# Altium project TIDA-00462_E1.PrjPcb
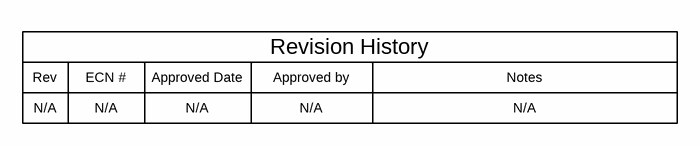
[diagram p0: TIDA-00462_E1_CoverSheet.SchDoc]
CopyrightYear: 2015; EVM_Orderable: N/A; PCB_Layout: Avinash; PCB_Rev: E1; PRJ_Customer: Public Release; PRJ_Engineer: FA&C; PRJ_Number: TIDA-00462; PRJ_Title: MSP430 MCU based Ultrasonic Distance Measurement; SCH_Rev: E1; TechSupport: http://www.ti.com/support; TID: TIDA-00462
4 sheets, 107 parts. Net scope: global (net labels, ports and power ports of the same name join across sheets).
Board file: TIDA-00462_E1.PcbDoc
Sheets:
  TIDA-00462_E1_CoverSheet.SchDoc
  TIDA-00462_E1_Power_Supply.SchDoc
  TIDA-00462_E1_MCU_US_TX_RX.SchDoc
  TIDA-00462_E1_TID_Hardware.SchDoc

## Sheet TIDA-00462_E1_CoverSheet.SchDoc: Block Diagram
size 431 x 279 mm; Date: Not shown in title block; ApprovedBy: Not shown in title block; CheckedBy: Not shown in title block; Author: Not shown in title block; CompanyName: Not shown in title block; DrawnBy: SY; Engineer: FA&C; Organization: Not shown in title block; Address1: Not shown in title block; Address2: Not shown in title block; Address3: Not shown in title block; Address4: Not shown in title block; DocumentNumber: 1; Revision: Use project parameter SCH_Rev; SheetNumber: 1; SheetTotal: 4; PageSetup: Record=PageOptions¦CenterHorizontal=True¦CenterVertical=True¦PrintScale=1.00¦XCorrection=1.00¦YCorrection=1.00¦PrintKind=0¦BorderSize=5000000¦LeftOffset=0¦BottomOffset=0¦Orientation=2¦PaperLength=1000¦PaperWidth=1000¦Scale=100¦PaperSource=15¦PrintQuality=600¦MediaType=1¦DitherType=10¦PaperKind=Letter¦PrintScaleMode=1

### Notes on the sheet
- Rev
- N/A
- ECN #
- Approved Date
- Approved by
- Revision History
- Notes

## Sheet TIDA-00462_E1_Power_Supply.SchDoc: Power Supply Circuitry & BP Connector
size 431 x 279 mm; Date: Not shown in title block; ApprovedBy: Not shown in title block; CheckedBy: Not shown in title block; Author: Not shown in title block; CompanyName: Not shown in title block; DrawnBy: SY; Engineer: FA&C; Organization: Not shown in title block; Address1: Not shown in title block; Address2: Not shown in title block; Address3: Not shown in title block; Address4: Not shown in title block; DocumentNumber: 1; Revision: Use project parameter SCH_Rev; SheetNumber: 2; SheetTotal: 4; PageSetup: Record=PageOptions¦CenterHorizontal=True¦CenterVertical=True¦PrintScale=1.00¦XCorrection=1.00¦YCorrection=1.00¦PrintKind=0¦BorderSize=5000000¦LeftOffset=0¦BottomOffset=0¦Orientation=2¦PaperLength=1000¦PaperWidth=1000¦Scale=100¦PaperSource=15¦PrintQuality=600¦MediaType=1¦DitherType=10¦PaperKind=Letter¦PrintScaleMode=1
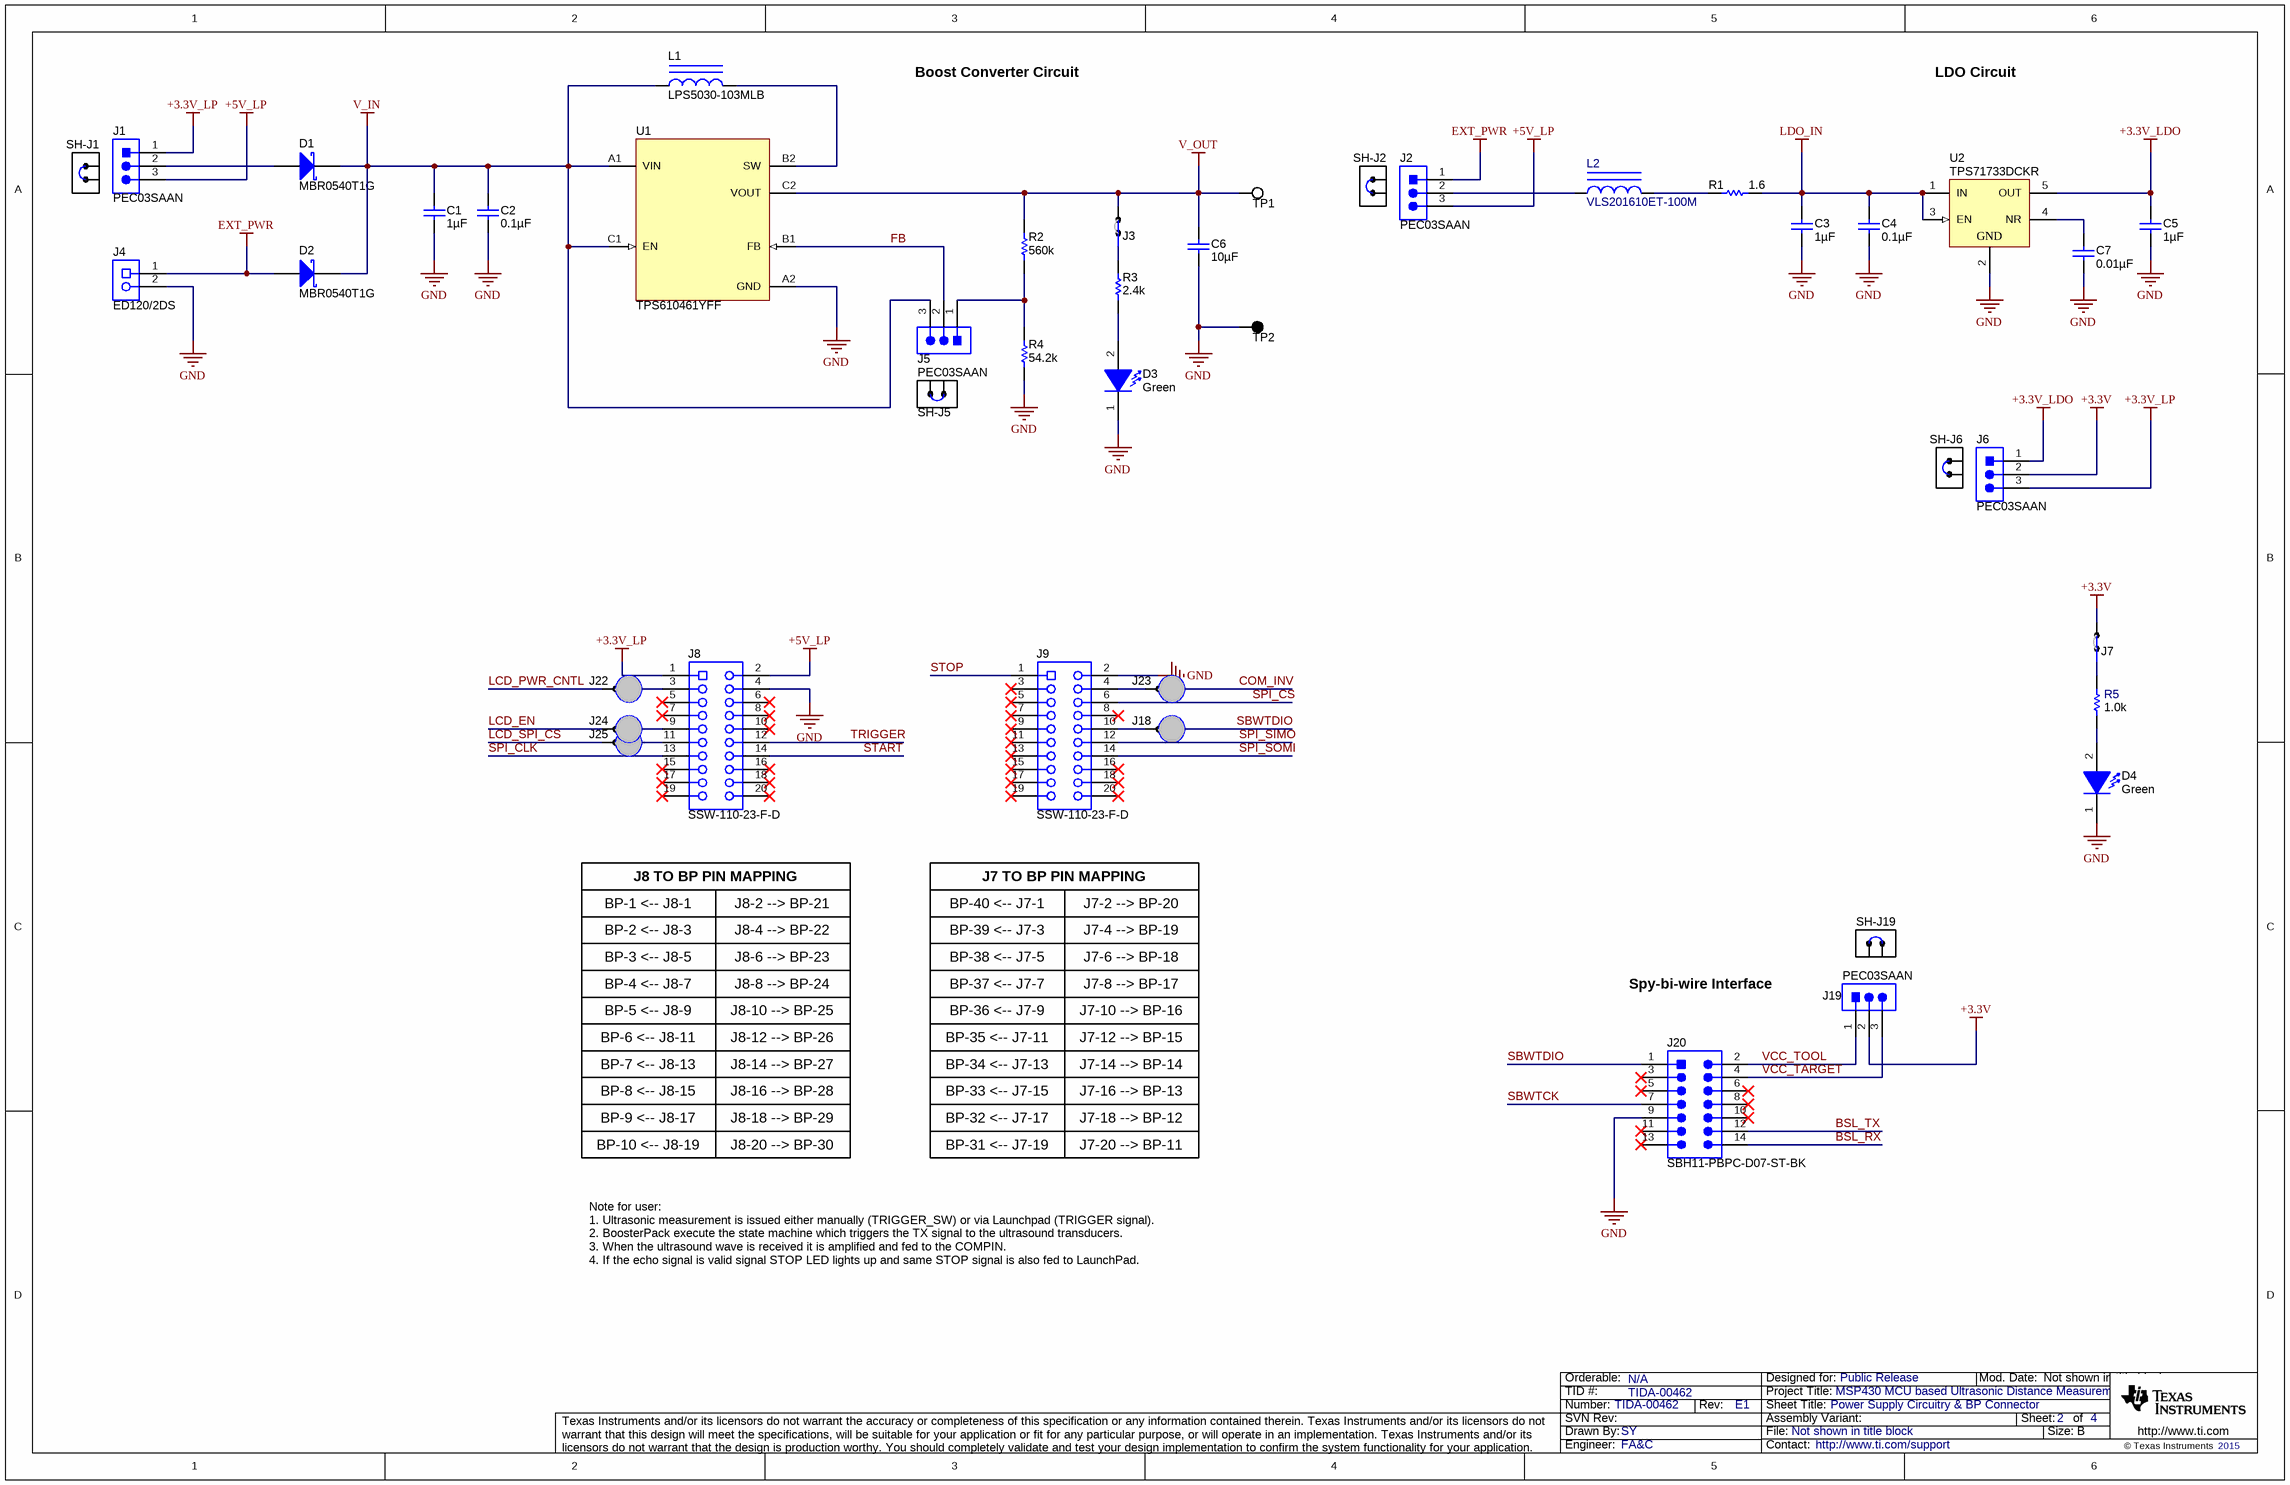
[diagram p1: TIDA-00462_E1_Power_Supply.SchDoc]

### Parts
C1  ValueDisplayed: 1µF  [0603]  (hidden comment: C1608X7R1C105K)
C2  ValueDisplayed: 0.1µF  [0603]  (hidden comment: C0603C104M4RACTU)
C3  ValueDisplayed: 1µF  [0603]  (hidden comment: GRM188R71E105KA12D)
C4  ValueDisplayed: 0.1µF  [0402]  (hidden comment: C1005X7R1H104K050BB)
C5  ValueDisplayed: 1µF  [0603]  (hidden comment: GRM188R71E105KA12D)
C6  ValueDisplayed: 10µF  [1206]  (hidden comment: GMK316AB7106KL)
C7  ValueDisplayed: 0.01µF  [0402]  (hidden comment: C1005X7R1C103K)
D1  MBR0540T1G  [SOD-123]
D2  MBR0540T1G  [SOD-123]
D3  value Green  [WL-SMCW_GREEN]  (hidden comment: 150060VS75000)
D4  value Green  [WL-SMCW_GREEN]  (hidden comment: 150060VS75000)
J1  PEC03SAAN  [CONN_PEC03SAAN]
J2  PEC03SAAN  [CONN_PEC03SAAN]
J3  923345-01-C  [3M_923345-01-C]  (value not drawn)
J4  ED120/2DS  [CONN_ED120-2DS]
J5  PEC03SAAN  [CONN_PEC03SAAN]
J6  PEC03SAAN  [CONN_PEC03SAAN]
J7  923345-01-C  [3M_923345-01-C]  (value not drawn)
J8  SSW-110-23-F-D  [CONN_SSW-110-23-F-D]
J9  SSW-110-23-F-D  [CONN_SSW-110-23-F-D]
J18  923345-01-C  [3M_923345-01-C]  (value not drawn)
J19  PEC03SAAN  [CONN_PEC03SAAN]
J20  SBH11-PBPC-D07-ST-BK  [CONN_SBH11-PBPC-D07-ST-BK]
J22  923345-01-C  [3M_923345-01-C]  (value not drawn)
J23  923345-01-C  [3M_923345-01-C]  (value not drawn)
J24  923345-01-C  [3M_923345-01-C]  (value not drawn)
J25  923345-01-C  [3M_923345-01-C]  (value not drawn)
L1  LPS5030-103MLB  [LPS5030]
L2  VLS201610ET-100M  [VLS201610]
R1  ValueDisplayed: 1.6  [0805]  (hidden comment: ERJ-6GEYJ1R6V)
R2  ValueDisplayed: 560k  [0603]  (hidden comment: RC0603FR-07560KL)
R3  ValueDisplayed: 2.4k  [0603]  (hidden comment: CRCW06032K40JNEA)
R4  ValueDisplayed: 54.2k  [0603]  (hidden comment: RT0603DRE0754K2L)
R5  value 1.0k  [0402]  (hidden comment: CRCW04021K00JNED)
SH-J1  969102-0000-DA  [SNT-100-BK-G]  (value not drawn)
SH-J2  969102-0000-DA  [SNT-100-BK-G]  (value not drawn)
SH-J5  969102-0000-DA  [SNT-100-BK-G]  (value not drawn)
SH-J6  969102-0000-DA  [SNT-100-BK-G]  (value not drawn)
SH-J19  969102-0000-DA  [SNT-100-BK-G]  (value not drawn)
TP1  5002  [Keystone5002]  (value not drawn)
TP2  5001  [Keystone5001]  (value not drawn)
U1  TPS610461YFF  [YFF0006AAAA]
U2  TPS71733DCKR  [DCK0005A_N]

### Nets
+3.3V: J6.2 J7.2 J19.2
+3.3V_LDO: C5.1 J6.1 U2.5(OUT)
+3.3V_LP: J1.1 J6.3 J8.1
+5V_LP: J1.3 J2.3 J8.2
EXT_PWR: D2.2(A) J2.1 J4.1
GND: C1.2 C2.2 C3.2 C4.2 C5.2 C6.2 C7.2 D3.1(K) D4.1(K) J4.2 J8.4 J9.2 J20.9 R4.1 TP2.1 U1.A2(GND) U2.2(GND)
LDO_IN: C3.1 C4.1 R1.2 U2.1(IN) U2.3(EN)
V_IN: C1.1 C2.1 D1.1(K) D2.1(K) J5.3 L1.1 U1.A1(VIN) U1.C1(EN)
V_OUT: C6.1 J3.2 R2.2 TP1.1 U1.C2(VOUT)
BSL_RX: J20.14
BSL_TX: J20.12
COM_INV: J23.1
FB: J5.2 U1.B1(FB)
LCD_EN: J24.2
LCD_PWR_CNTL: J22.2
LCD_SPI_CS: J25.2
SBWTCK: J20.7
SBWTDIO: J18.1 J20.1
SPI_CLK: J8.13
SPI_CS: J9.6
SPI_SIMO: J9.12
SPI_SOMI: J9.14
START: J8.14
STOP: J9.1
TRIGGER: J8.12
VCC_TARGET: J19.3 J20.4
VCC_TOOL: J19.1 J20.2
NetC7_1: C7.1 U2.4(NR)
NetD1_2: D1.2(A) J1.2
NetD3_2: D3.2(A) R3.1
NetD4_2: D4.2(A) R5.2
NetJ2_2: J2.2 L2.1
NetJ3_1: J3.1 R3.2
NetJ5_1: J5.1 R2.1 R4.2
NetJ7_1: J7.1 R5.1
NetJ8_3: J8.3 J22.1
NetJ8_9: J8.9 J24.1
NetJ8_11: J8.11 J25.1
NetJ9_4: J9.4 J23.2
NetJ9_10: J9.10 J18.2
NetL1_2: L1.2 U1.B2(SW)
NetL2_2: L2.2 R1.1

Not connected (* = marked no-connect by the designer): J8 5* 6* 7* 8* 10* 15* 16* 17* 18* 19* 20*; J9 3* 5* 7* 8* 9* 11* 13* 15* 16* 17* 18* 19* 20*; J20 3* 5* 6* 8* 10* 11* 13*

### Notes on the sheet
- Boost Converter Circuit
- LDO Circuit
- BP-1 <-- J8-1
- J8 TO BP PIN MAPPING
- J8-2 --> BP-21
- BP-40 <-- J7-1
- J7 TO BP PIN MAPPING
- J7-2 --> BP-20
- BP-2 <-- J8-3
- BP-3 <-- J8-5
- J8-4 --> BP-22
- J8-6 --> BP-23
- BP-39 <-- J7-3
- BP-38 <-- J7-5
- J7-4 --> BP-19
- J7-6 --> BP-18
- BP-4 <-- J8-7
- BP-5 <-- J8-9
- BP-6 <-- J8-11
- J8-8 --> BP-24
- J8-10 --> BP-25
- J8-12 --> BP-26
- BP-37 <-- J7-7
- BP-36 <-- J7-9
- BP-35 <-- J7-11
- J7-8 --> BP-17
- J7-10 --> BP-16
- J7-12 --> BP-15
- Spy-bi-wire Interface
- BP-7 <-- J8-13
- BP-8 <-- J8-15
- J8-14 --> BP-27
- J8-16 --> BP-28
- BP-34 <-- J7-13
- BP-33 <-- J7-15
- J7-14 --> BP-14
- J7-16 --> BP-13
- BP-10 <-- J8-19
- BP-9 <-- J8-17
- J8-18 --> BP-29
- J8-20 --> BP-30
- BP-31 <-- J7-19
- BP-32 <-- J7-17
- J7-18 --> BP-12
- J7-20 --> BP-11
- Note for user:
  1. Ultrasonic measurement is issued either manually (TRIGGER_SW) or via Launchpad (TRIGGER signal).
  2. BoosterPack execute the state machine which triggers the TX signal to the ultrasound transducers.
  3. When the ultrasound wave is received it is amplified and fed to the COMPIN.
  4. If the echo signal is valid signal STOP LED lights up and same STOP signal is also fed to LaunchPad.

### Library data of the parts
C1 = C1608X7R1C105K: CAP, CERM, 1 µF, 16 V, +/- 10%, X7R, 0603; Manufacturer: TDK; Polarized: N; CompType: Capacitor; Value: 1uF; U/M: EA; Cap_F: 0.000001; Tolerance_%: 10; ESR_ohm: 0.0057; Value1: 0.0057 ohm; VDC_V: 16; Value2: 16V; TaMin_C: -55; TaMax_C: 125
C2 = C0603C104M4RACTU: CAP, CERM, 0.1 µF, 16 V, +/- 20%, X7R, 0603; Manufacturer: Kemet; Polarized: N; CompType: Capacitor; Value: 0.1uF; U/M: EA; Cap_F: 0.0000001; Tolerance_%: 20; Value1: Unknown; VDC_V: 16; Value2: 16V; TaMin_C: -55; TaMax_C: 125
C3 C5 = GRM188R71E105KA12D: CAP, CERM, 1 µF, 25 V, +/- 10%, X7R, 0603; Manufacturer: MuRata; Polarized: N; CompType: Capacitor; Value: 1uF; U/M: EA; Cap_F: 0.000001; Tolerance_%: 10; Value1: Unknown; VDC_V: 25; Value2: 25V; TaMin_C: -55; TaMax_C: 125
C4 = C1005X7R1H104K050BB: CAP, CERM, 0.1 µF, 50 V, +/- 10%, X7R, 0402; Manufacturer: TDK; Polarized: N; CompType: Capacitor; Value: 0.1uF; U/M: EA; Cap_F: 0.0000001; Tolerance_%: 10; Value1: Unknown; VDC_V: 50; Value2: 50V; TaMin_C: -55; TaMax_C: 125
C6 = GMK316AB7106KL: CAP, CERM, 10 µF, 35 V, +/- 10%, X7R, 1206; Manufacturer: Taiyo Yuden; Polarized: N; CompType: Capacitor; Value: 10uF; U/M: EA; Cap_F: 0.00001; Tolerance_%: 10; Value1: Unknown; VDC_V: 35; Value2: 35V; TaMin_C: -55; TaMax_C: 125
C7 = C1005X7R1C103K: CAP, CERM, 0.01 µF, 16 V, +/- 10%, X7R, 0402; Manufacturer: TDK; Polarized: N; CompType: Capacitor; Value: 0.01uF; U/M: EA; Cap_F: 0.00000001; Tolerance_%: 10; ESR_ohm: 0.0623; Value1: 0.0623 ohm; VDC_V: 16; Value2: 16V; TaMin_C: -55; TaMax_C: 125
D1 D2 = MBR0540T1G: Diode, Schottky, 40V, 0.5A, SOD-123; Manufacturer: ON Semiconductor; U/M: EA; Vf_V: 0.51; Value2: 0.51V; Io_A: 0.5; Vr_V: 40; TJmax_C: 150; RJC_CperW: 118
D3 D4 = 150060VS75000: LED, Green, SMD; Manufacturer: Wurth Elektronik eiSos; Type: AlInGaP; Vf_V: 2; Value2: 2V; Io_A: 0.02; Value1: W; U/M: EA
J1 J2 J5 J6 J19 = PEC03SAAN: Header, 100mil, 3x1, Tin plated, TH; Manufacturer: Sullins Connector Solutions; SymbolCreator: a0799628; U/M: EA
J3 J7 J18 J22-J25 = 923345-01-C: Jumper Wire, 100mil spacing, pkg of 200, TH; Manufacturer: 3M; SymbolCreator: Altium; U/M: EA
J4 = ED120/2DS: TERMINAL BLOCK 5.08MM VERT 2POS, TH; Manufacturer: On-Shore Technology; SymbolCreator: a0412235; U/M: EA
J8 J9 = SSW-110-23-F-D: Connector, Receptacle, 100mil, 10x2, Gold plated, TH; Manufacturer: Samtec; SymbolCreator: a0412235; U/M: EA
J20 = SBH11-PBPC-D07-ST-BK: Header (shrouded), 100 mil, 7x2, Gold plated, TH; Manufacturer: Sullins Connector Solutions; SymbolCreator: a0412235; CompType: Connector; U/M: EA
L1 = LPS5030-103MLB: Inductor, Shielded Drum Core, Ferrite, 10 µH, 1.4 A, 0.13 ohm, SMD; Manufacturer: Coilcraft; Value: 10uH; Ind_H: 10.0E-6; ValueDisplayed: 10µH; Imax_A: 1.4; Irms: 1.5A @ 40C rise; Isat: 1.4A @ 30% inductance drop; DCR_ohm: 0.13; Value2: 1.4A
L2 = VLS201610ET-100M: Inductor, Shielded, Ferrite, 10uH, 0.4A, 1.38 ohm, SMD; Manufacturer: TDK; Ind_H: 10.0E-6; ValueDisplayed: 10µH; Imax_A: 0.4; Irms: 0.42A @ 40C rise; Isat: 0.4A @ 30% inductance drop; DCR_ohm: 1.38; U/M: EA
R1 = ERJ-6GEYJ1R6V: RES, 1.6, 5%, 0.125 W, 0805; Manufacturer: Panasonic; CompType: Resistor; Value: 1.6; Value_Code: 1R60; Tolerance_%: 5; Power_W: 0.125; Value2: 0.125W; VDC_V: 150; TempCo: 600 ppm/C; EIA_Code: E24; U/M: EA
R2 = RC0603FR-07560KL: RES, 560 k, 1%, 0.1 W, 0603; Manufacturer: Yageo America; CompType: Resistor; Value: 560k; Res_ohm: 560000; Tolerance_%: 1; Power_W: 0.1; Value2: 0.1W; VDC_V: 150; TempCo: 200 ppm/C; U/M: EA
R3 = CRCW06032K40JNEA: RES, 2.4 k, 5%, 0.1 W, 0603; Manufacturer: Vishay-Dale; CompType: Resistor; Value: 2.4k; Res_ohm: 2400; Value_Code: 2k40; Tolerance_%: 5; Power_W: 0.1; Value2: 0.1W; VDC_V: 75; TempCo: 200 ppm/C; EIA_Code: E24; U/M: EA
R4 = RT0603DRE0754K2L: RES, 54.2 k, 0.5%, 0.1 W, 0603; Manufacturer: Yageo America; CompType: Resistor; Value: 54.2k; Res_ohm: 54200; Value_Code: 54k2; Tolerance_%: 0.5; Power_W: 0.1; Value2: 0.1W; VDC_V: 75; TempCo: 50 ppm/C; EIA_Code: E192; U/M: EA
R5 = CRCW04021K00JNED: RES, 1.0k ohm, 5%, 0.063W, 0402; Manufacturer: Vishay-Dale; CompType: Resistor; Res_ohm: 1000; Value_Code: 1k00; Tolerance_%: 5; Power_W: 0.063; VDC_V: 50; TempCo: 200 ppm/C; EIA_Code: E24; U/M: EA
SH-J1 SH-J2 SH-J5 SH-J6 SH-J19 = 969102-0000-DA: Shunt, 100mil, Gold plated, Black; Manufacturer: 3M; Alternate Manufacturer: Samtec; Value: 1x2; Note: You can "mate" this to a header by matching the designator.  i.e. use SH-J3 for header J3
TP1 = 5002: Test Point, Miniature, White, TH; Manufacturer: Keystone; CompType: Test Point Loop; U/M: EA
TP2 = 5001: Test Point, Miniature, Black, TH; Manufacturer: Keystone; CompType: Test Point Loop; U/M: EA
U1 = TPS610461YFF: 28-V Output Voltage Boost Converter, YFF0006AAAA; Manufacturer: Texas Instruments; SymbolCreator: Altium; CompType: IC; U/M: EA
U2 = TPS71733DCKR: Single Output High PSRR LDO, 150 mA, Fixed 3.3 V Output, 2.5 to 6.5 V Input, with Low IQ, 5-pin SC70 (DCK), -40 to 85 degC, Green (RoHS & no Sb/Br); Manufacturer: Texas Instruments; Alternate Manufacturer: None; Alternate PartNumber: Equivalent; Accuracy(%): 3; Fixed Output Options(V): 3.3; Iout(Max)(A): 0.15; Iq(Typ)(mA): 0.05; SubFamily: Single Channel LDO; Vdo(Typ)(mV): 170; Vin(Max)(V): 6.5; Vin(Min)(V): 2.5

## Sheet TIDA-00462_E1_MCU_US_TX_RX.SchDoc: MSP430 MCU & US Sensor (TX & RX) Circuitry
size 431 x 279 mm; Date: Not shown in title block; ApprovedBy: Not shown in title block; CheckedBy: Not shown in title block; Author: Not shown in title block; CompanyName: Not shown in title block; DrawnBy: SY; Engineer: FA&C; Organization: Not shown in title block; Address1: Not shown in title block; Address2: Not shown in title block; Address3: Not shown in title block; Address4: Not shown in title block; DocumentNumber: 1; Revision: Use project parameter SCH_Rev; SheetNumber: 3; SheetTotal: 4; PageSetup: Record=PageOptions¦CenterHorizontal=True¦CenterVertical=True¦PrintScale=1.00¦XCorrection=1.00¦YCorrection=1.00¦PrintKind=0¦BorderSize=5000000¦LeftOffset=0¦BottomOffset=0¦Orientation=2¦PaperLength=1000¦PaperWidth=1000¦Scale=100¦PaperSource=15¦PrintQuality=600¦MediaType=1¦DitherType=10¦PrintScaleMode=1¦PaperKind=Letter
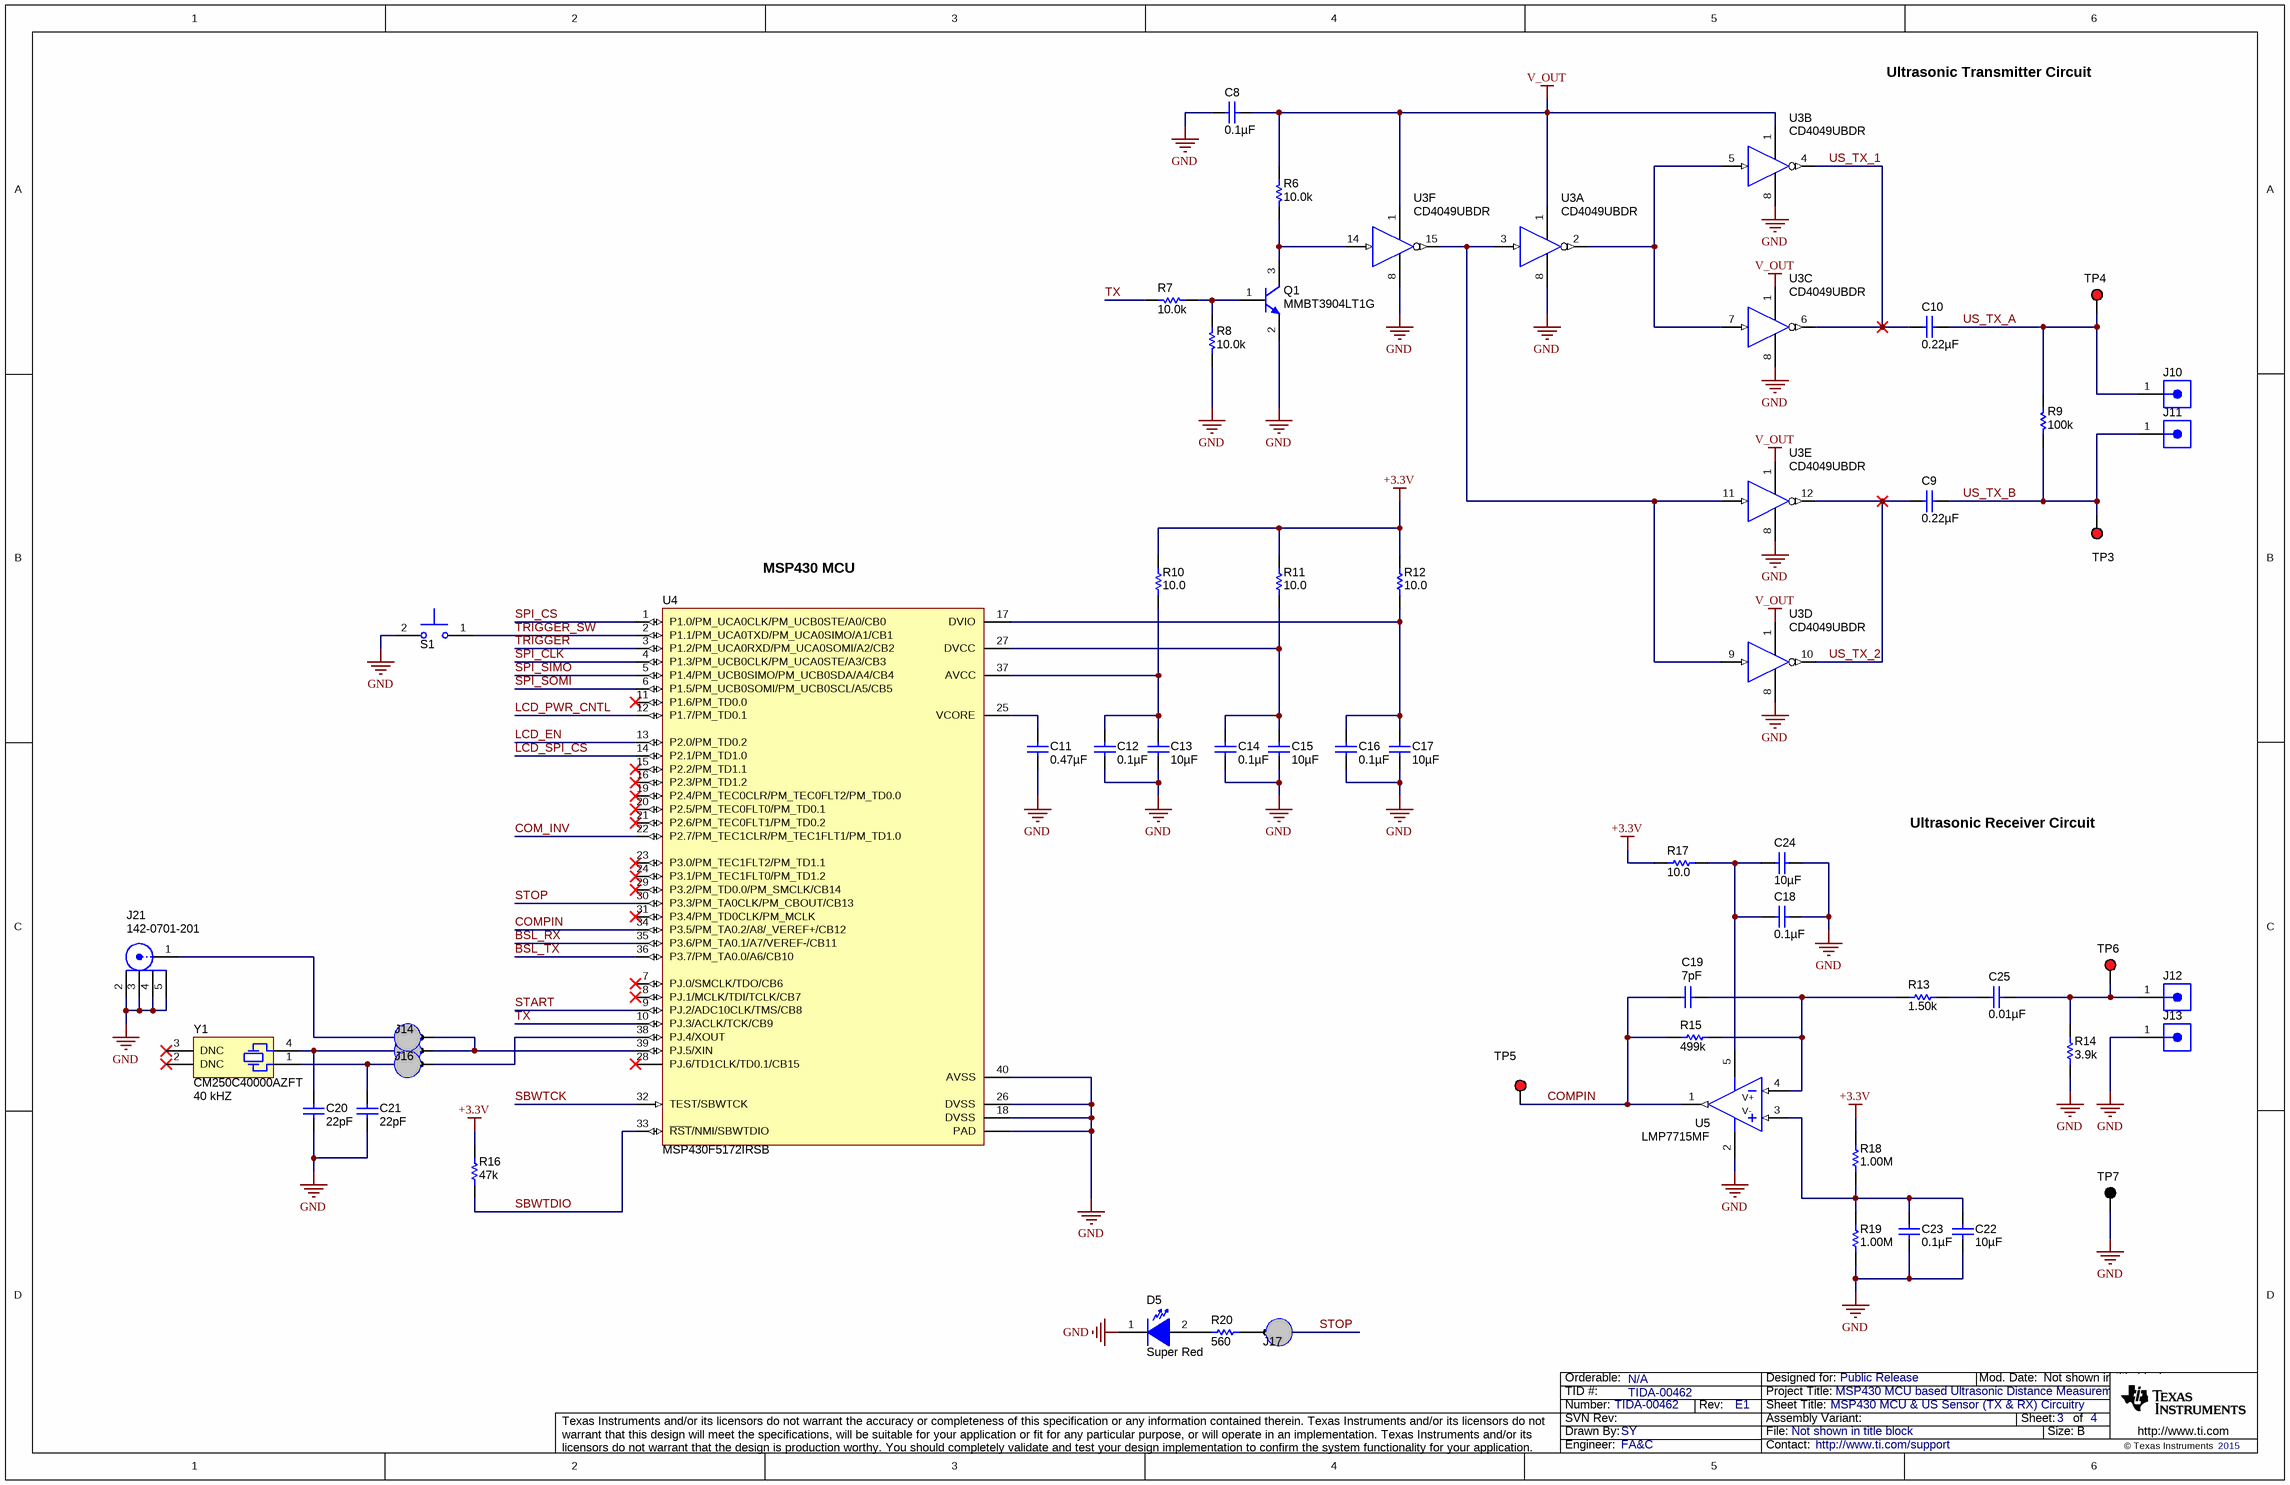
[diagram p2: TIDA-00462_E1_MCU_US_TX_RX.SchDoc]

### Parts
C8  ValueDisplayed: 0.1µF  [0402]  (hidden comment: C1005X7R1H104K050BB)
C9  ValueDisplayed: 0.22µF  [0603]  (hidden comment: C1608X7R1H224K080AB)
C10  ValueDisplayed: 0.22µF  [0603]  (hidden comment: C1608X7R1H224K080AB)
C11  ValueDisplayed: 0.47µF  [0603S]  (hidden comment: GRM188R70J474KA01D)
C12  ValueDisplayed: 0.1µF  [0402S]  (hidden comment: GRM155R70J104KA01D)
C13  ValueDisplayed: 10µF  [0402]  (hidden comment: CL05A106MQ5NUNC)
C14  ValueDisplayed: 0.1µF  [0402S]  (hidden comment: GRM155R70J104KA01D)
C15  ValueDisplayed: 10µF  [0402]  (hidden comment: CL05A106MQ5NUNC)
C16  ValueDisplayed: 0.1µF  [0402S]  (hidden comment: GRM155R70J104KA01D)
C17  ValueDisplayed: 10µF  [0402]  (hidden comment: CL05A106MQ5NUNC)
C18  ValueDisplayed: 0.1µF  [0402]  (hidden comment: C1005X7R1H104K050BB)
C19  ValueDisplayed: 7pF  [0805_HV]  (hidden comment: CC0805DRNP09BN7R0)
C20  ValueDisplayed: 22pF  [0402]  (hidden comment: C1005C0G1H220J050BA)
C21  ValueDisplayed: 22pF  [0402]  (hidden comment: C1005C0G1H220J050BA)
C22  ValueDisplayed: 10µF  [0805_145]  (hidden comment: 885012207026)
C23  ValueDisplayed: 0.1µF  [0402]  (hidden comment: C1005X7R1H104K050BB)
C24  ValueDisplayed: 10µF  [0402]  (hidden comment: CL05A106MQ5NUNC)
C25  ValueDisplayed: 0.01µF  [0603]  (hidden comment: GRM188R71C103KA01D)
D5  value Super Red  [WL-SMCW_RED]  (hidden comment: 150060SS75000)
J10  TSW-101-17-T-S  [Samtec_TSW-101-17-T-S]  (value not drawn)
J11  TSW-101-17-T-S  [Samtec_TSW-101-17-T-S]  (value not drawn)
J12  TSW-101-17-T-S  [Samtec_TSW-101-17-T-S]  (value not drawn)
J13  TSW-101-17-T-S  [Samtec_TSW-101-17-T-S]  (value not drawn)
J14  923345-01-C  [3M_923345-01-C]  (value not drawn)
J15  923345-01-C  [3M_923345-01-C]  (value not drawn)
J16  923345-01-C  [3M_923345-01-C]  (value not drawn)
J17  923345-01-C  [3M_923345-01-C]  (value not drawn)
J21  142-0701-201  [Johnson_142-0701-20x]
Q1  MMBT3904LT1G  [SOT-23]
R6  ValueDisplayed: 10.0k  [0603]  (hidden comment: ERJ-3EKF1002V)
R7  ValueDisplayed: 10.0k  [0603]  (hidden comment: ERJ-3EKF1002V)
R8  ValueDisplayed: 10.0k  [0603]  (hidden comment: ERJ-3EKF1002V)
R9  ValueDisplayed: 100k  [0603]  (hidden comment: RC0603FR-07100KL)
R10  value 10.0  [0603]  (hidden comment: CRCW060310R0FKEA)
R11  value 10.0  [0603]  (hidden comment: CRCW060310R0FKEA)
R12  value 10.0  [0603]  (hidden comment: CRCW060310R0FKEA)
R13  ValueDisplayed: 1.50k  [0603]  (hidden comment: ERJ-3EKF1501V)
R14  ValueDisplayed: 3.9k  [0603]  (hidden comment: CRCW06033K90JNEA)
R15  ValueDisplayed: 499k  [0603]  (hidden comment: CRCW0603499KFKEA)
R16  value 47k  [0402]  (hidden comment: CRCW040247K0JNED)
R17  value 10.0  [0603]  (hidden comment: CRCW060310R0FKEA)
R18  ValueDisplayed: 1.00M  [0603]  (hidden comment: CRCW06031M00FKEA)
R19  ValueDisplayed: 1.00M  [0603]  (hidden comment: CRCW06031M00FKEA)
R20  ValueDisplayed: 560  [0603]  (hidden comment: CRCW0603560RJNEA)
S1  SKRKAEE010  [SW_SKRKAEE010]  (value not drawn)
TP3  5000  [Keystone5000]  (value not drawn)
TP4  5000  [Keystone5000]  (value not drawn)
TP5  5000  [Keystone5000]  (value not drawn)
TP6  5000  [Keystone5000]  (value not drawn)
TP7  5001  [Keystone5001]  (value not drawn)
U3  CD4049UBDR  [D0016A_N]  (parts A,B,C,D,E,F of 7)
U4  MSP430F5172IRSB  [RSB0040B]
U5  LMP7715MF  [DBV0005A_N]
Y1  CM250C40000AZFT  Frequency: 40 kHZ  [CFM_CM250C]

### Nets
+3.3V: R10.2 R11.2 R12.2 R16.2 R17.2 R18.2
GND: C8.2 C11.2 C12.2 C13.2 C14.2 C15.2 C16.2 C17.2 C18.2 C20.2 C21.2 C22.2 C23.2 C24.2 D5.1(K) J13.1 J21.2 J21.3 J21.4 J21.5 Q1.2(E) R8.2 R14.1 R19.1 S1.2 TP7.1 U3.8(VSS) U4.18(DVSS) U4.26(DVSS) U4.40(AVSS) U4.41(PAD) U5.2(V-)
V_OUT: C8.1 R6.2 U3.1(VCC)
BSL_RX: U4.35(P3.6/PM_TA0.1/A7/VEREF-/CB11)
BSL_TX: U4.36(P3.7/PM_TA0.0/A6/CB10)
COM_INV: U4.22(P2.7/PM_TEC1CLR/PM_TEC1FLT1/PM_TD1.0)
COMPIN: C19.2 R15.1 TP5.1 U4.34(P3.5/PM_TA0.2/A8/_VEREF+/CB12) U5.1(OUT)
LCD_EN: U4.13(P2.0/PM_TD0.2)
LCD_PWR_CNTL: U4.12(P1.7/PM_TD0.1)
LCD_SPI_CS: U4.14(P2.1/PM_TD1.0)
SBWTCK: U4.32(TEST/SBWTCK)
SBWTDIO: R16.1 U4.33(~{RST}/NMI/SBWTDIO)
SPI_CLK: U4.4(P1.3/PM_UCB0CLK/PM_UCA0STE/A3/CB3)
SPI_CS: U4.1(P1.0/PM_UCA0CLK/PM_UCB0STE/A0/CB0)
SPI_SIMO: U4.5(P1.4/PM_UCB0SIMO/PM_UCB0SDA/A4/CB4)
SPI_SOMI: U4.6(P1.5/PM_UCB0SOMI/PM_UCB0SCL/A5/CB5)
START: U4.9(PJ.2/ADC10CLK/TMS/CB8)
STOP: J17.1 U4.30(P3.3/PM_TA0CLK/PM_CBOUT/CB13)
TRIGGER: U4.3(P1.2/PM_UCA0RXD/PM_UCA0SOMI/A2/CB2)
TRIGGER_SW: S1.1 U4.2(P1.1/PM_UCA0TXD/PM_UCA0SIMO/A1/CB1)
TX: R7.1 U4.10(PJ.3/ACLK/TCK/CB9)
US_TX_1: C10.2 U3.4(Y) U3.6(Y)
US_TX_2: C9.2 U3.10(Y) U3.12(Y)
US_TX_A: C10.1 J10.1 R9.1 TP4.1
US_TX_B: C9.1 J11.1 R9.2 TP3.1
NetC11_1: C11.1 U4.25(VCORE)
NetC12_1: C12.1 C13.1 R10.1 U4.37(AVCC)
NetC14_1: C14.1 C15.1 R11.1 U4.27(DVCC)
NetC16_1: C16.1 C17.1 R12.1 U4.17(DVIO)
NetC18_1: C18.1 C24.1 R17.1 U5.5(V+)
NetC19_1: C19.1 R13.1 R15.2 U5.4(IN-)
NetC20_1: C20.1 J15.1 Y1.4
NetC21_1: C21.1 J16.1 Y1.1
NetC22_1: C22.1 C23.1 R18.1 R19.2 U5.3(IN+)
NetC25_1: C25.1 J12.1 R14.2 TP6.1
NetC25_2: C25.2 R13.2
NetD5_2: D5.2(A) R20.1
NetJ14_1: J14.1 J21.1
NetJ14_2: J14.2 J15.2 U4.39(PJ.5/XIN)
NetJ16_2: J16.2 U4.38(PJ.4/XOUT)
NetJ17_2: J17.2 R20.2
NetQ1_1: Q1.1(B) R7.2 R8.1
NetQ1_3: Q1.3(C) R6.1 U3.14(A)
NetU3_2: U3.2(Y) U3.5(A) U3.7(A)
NetU3_3: U3.3(A) U3.9(A) U3.11(A) U3.15(Y)

Not connected (* = marked no-connect by the designer): U4 7(PJ.0/SMCLK/TDO/CB6)* 8(PJ.1/MCLK/TDI/TCLK/CB7)* 11(P1.6/PM_TD0.0)* 15(P2.2/PM_TD1.1)* 16(P2.3/PM_TD1.2)* 19(P2.4/PM_TEC0CLR/PM_TEC0FLT2/PM_TD0.0)* 20(P2.5/PM_TEC0FLT0/PM_TD0.1)* 21(P2.6/PM_TEC0FLT1/PM_TD0.2)* 23(P3.0/PM_TEC1FLT2/PM_TD1.1)* 24(P3.1/PM_TEC1FLT0/PM_TD1.2)* 28(PJ.6/TD1CLK/TD0.1/CB15)* 29(P3.2/PM_TD0.0/PM_SMCLK/CB14)* 31(P3.4/PM_TD0CLK/PM_MCLK)*; Y1 2(DNC)* 3(DNC)*

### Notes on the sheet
- Ultrasonic Transmitter Circuit
- (near U4) MSP430 MCU
- Ultrasonic Receiver Circuit

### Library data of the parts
C8 C18 C23 = C1005X7R1H104K050BB: as C4 on sheet TIDA-00462_E1_Power_Supply
C9 C10 = C1608X7R1H224K080AB: CAP, CERM, 0.22 µF, 50 V, +/- 10%, X7R, 0603; Manufacturer: TDK; Polarized: N; CompType: Capacitor; Value: 0.22uF; U/M: EA; Cap_F: 0.00000022; Tolerance_%: 10; Value1: Unknown; VDC_V: 50; Value2: 50V; TaMin_C: -55; TaMax_C: 125
C11 = GRM188R70J474KA01D: CAP, CERM, 0.47uF, 6.3V, +/-10%, X7R, 0603; Manufacturer: MuRata; Polarized: N; CompType: Capacitor; U/M: EA; Cap_F: 0.00000047; Tolerance_%: 10; Value1: Unknown; VDC_V: 6.3; TaMin_C: -55; TaMax_C: 125; Cap_Case: 0603
C12 C14 C16 = GRM155R70J104KA01D: CAP, CERM, 0.1uF, 6.3V, +/-10%, X7R, 0402; Manufacturer: MuRata; Polarized: N; CompType: Capacitor; U/M: EA; Cap_F: 0.0000001; Tolerance_%: 10; Value1: Unknown; VDC_V: 6.3; TaMin_C: -55; TaMax_C: 125; Cap_Case: 0402
C13 C15 C17 C24 = CL05A106MQ5NUNC: CAP, CERM, 10uF, 6.3V, +/-20%, X5R, 0402; Manufacturer: Samsung; Polarized: N; CompType: Capacitor; U/M: EA; Cap_F: 0.00001; Tolerance_%: 20; Value1: Unknown; VDC_V: 6.3; TaMin_C: -55; TaMax_C: 85
C19 = CC0805DRNP09BN7R0: CAP, CERM, 7 pF, 50 V, +/- 7%, C0G/NP0, 0805; Manufacturer: Yageo America; Polarized: N; CompType: Capacitor; Value: 7pF; U/M: EA; Cap_F: 0.000000000007; Tolerance_%: 7; Value1: Unknown; VDC_V: 50; Value2: 50V; TaMin_C: -55; TaMax_C: 125; Cap_Case: 0805
C20 C21 = C1005C0G1H220J050BA: CAP, CERM, 22 pF, 50 V, +/- 5%, C0G/NP0, 0402; Manufacturer: TDK; Polarized: N; CompType: Capacitor; Value: 22pF; U/M: EA; Cap_F: 0.000000000022; Tolerance_%: 5; Value1: Unknown; VDC_V: 50; Value2: 50V; TaMin_C: -55; TaMax_C: 125
C22 = 885012207026: CAP, CERM, 10 µF, 10 V, +/- 10%, X7R, 0805; Manufacturer: Wurth Elektronik; Polarized: N; CompType: Capacitor; Value: 10uF; U/M: EA; Cap_F: 0.00001; Tolerance_%: 10; Value1: Unknown; Value2: 10V; TaMin_C: -55; TaMax_C: 125; Cap_Case: 0805
C25 = GRM188R71C103KA01D: CAP, CERM, 0.01 µF, 16 V, +/- 10%, X7R, 0603; Manufacturer: MuRata; Polarized: N; CompType: Capacitor; Value: 0.01uF; U/M: EA; Cap_F: 0.00000001; Tolerance_%: 10; Value1: Unknown; VDC_V: 16; Value2: 16V; TaMin_C: -55; TaMax_C: 125
D5 = 150060SS75000: LED, Super Red, SMD; Manufacturer: Wurth Elektronik eiSos; Type: AlInGaP; Vf_V: 1.9; Value2: 1.9V; Io_A: 0.02; Value1: W; U/M: EA
J10-J13 = TSW-101-17-T-S: Header, 100mil, 1x1, Tin, TH; Manufacturer: Samtec; SymbolCreator: a0412235; U/M: EA
J14-J17 = 923345-01-C: as J3 on sheet TIDA-00462_E1_Power_Supply
J21 = 142-0701-201: Connector, TH, SMA; Manufacturer: Emerson Network Power; SymbolCreator: X0208326; U/M: EA
Q1 = MMBT3904LT1G, ON Semiconductor: Transistor, NPN, 40 V, 0.2 A, SOT-23; CompType: BJT; PNP: 0; NPN: 1; Vceo_V: 40; Vcesat1_V: 0.3; Value: 40 V; IcRated_A: 0.2; Value1: 0.2 A; HfeMax: 300; TaMin_C: -55; TaMax_C: 150; U/M: EA
R6-R8 = ERJ-3EKF1002V: RES, 10.0 k, 1%, 0.1 W, 0603; Manufacturer: Panasonic; CompType: Resistor; Value: 10.0k; Res_ohm: 10000; Value_Code: 10k0; Tolerance_%: 1; Power_W: 0.1; Value2: 0.1W; VDC_V: 75; TempCo: 100 ppm/C; EIA_Code: E96; U/M: EA
R9 = RC0603FR-07100KL: RES, 100 k, 1%, 0.1 W, 0603; Manufacturer: Yageo America; CompType: Resistor; Value: 100k; Res_ohm: 100000; Tolerance_%: 1; Power_W: 0.1; Value2: 0.1W; VDC_V: 150; TempCo: 200 ppm/C; EIA_Code: E96; U/M: EA
R10-R12 R17 = CRCW060310R0FKEA: RES, 10.0 ohm, 1%, 0.1W, 0603; Manufacturer: Vishay-Dale; CompType: Resistor; Res_ohm: 10; Value_Code: 10R0; Tolerance_%: 1; Power_W: 0.1; VDC_V: 75; TempCo: 100 ppm/C; EIA_Code: E96; U/M: EA
R13 = ERJ-3EKF1501V: RES, 1.50 k, 1%, 0.1 W, 0603; Manufacturer: Panasonic; CompType: Resistor; Value: 1.50k; Res_ohm: 1500; Value_Code: 1k50; Tolerance_%: 1; Power_W: 0.1; Value2: 0.1W; VDC_V: 75; TempCo: 100 ppm/C; EIA_Code: E96; U/M: EA
R14 = CRCW06033K90JNEA: RES, 3.9 k, 5%, 0.1 W, 0603; Manufacturer: Vishay-Dale; CompType: Resistor; Value: 3.9k; Res_ohm: 3900; Value_Code: 3k90; Tolerance_%: 5; Power_W: 0.1; Value2: 0.1W; VDC_V: 75; TempCo: 200 ppm/C; EIA_Code: E24; U/M: EA
R15 = CRCW0603499KFKEA: RES, 499 k, 1%, 0.1 W, 0603; Manufacturer: Vishay-Dale; CompType: Resistor; Value: 499k; Res_ohm: 499000; Tolerance_%: 1; Power_W: 0.1; Value2: 0.1W; VDC_V: 75; TempCo: 100 ppm/C; EIA_Code: E96; U/M: EA
R16 = CRCW040247K0JNED: RES, 47k ohm, 5%, 0.063W, 0402; Manufacturer: Vishay-Dale; CompType: Resistor; Res_ohm: 47000; Value_Code: 47k0; Tolerance_%: 5; Power_W: 0.063; VDC_V: 50; TempCo: 200 ppm/C; EIA_Code: E24; U/M: EA
R18 R19 = CRCW06031M00FKEA: RES, 1.00 M, 1%, 0.1 W, 0603; Manufacturer: Vishay-Dale; CompType: Resistor; Value: 1.00Meg; Res_ohm: 1000000; Value_Code: 1M00; Tolerance_%: 1; Power_W: 0.1; Value2: 0.1W; VDC_V: 75; TempCo: 100 ppm/C; EIA_Code: E96; U/M: EA
R20 = CRCW0603560RJNEA: RES, 560, 5%, 0.1 W, 0603; Manufacturer: Vishay-Dale; CompType: Resistor; Value: 560; Value_Code: 560R; Tolerance_%: 5; Power_W: 0.1; Value2: 0.1W; VDC_V: 75; TempCo: 200 ppm/C; EIA_Code: E24; U/M: EA
S1 = SKRKAEE010: Switch, Push Button, SMD; Manufacturer: Alps; SymbolCreator: a0412235; Circuit: SPST-NO; VDC_V: 12; SwitchFunction: Off-Mom; PositionCount: 1; CurrentRating_mA: 50
TP3-TP6 = 5000: Test Point, Miniature, Red, TH; Manufacturer: Keystone; CompType: Test Point Loop; U/M: EA
TP7 = 5001: as TP2 on sheet TIDA-00462_E1_Power_Supply
U3 = CD4049UBDR: CMOS Hex Buffer/Converters, D0016A; Alternate PartNumber: CD4049UBDT; Manufacturer: Texas Instruments; SymbolCreator: a0411947; CompType: IC; U/M: EA
U4 = MSP430F5172IRSB: Mixed Signal Microcontroller, RSB0040B; Alternate Manufacturer: None; Manufacturer: Texas Instruments; SymbolCreator: a0411947; CompType: IC; U/M: EA
U5 = LMP7715MF: 1.8V Precison, Single Low Noise CMOS Input Op Amp, DBV0005A; Manufacturer: Texas Instruments; CompType: OpAmp IC
Y1 = CM250C40000AZFT: Crystal, 40kHz, 12.5pF, SMD; Manufacturer: Citizen Finetech Miyota; SymbolCreator: a0411947; U/M: EA; TaMin_C: -40; TaMax_C: 85; Frequency Stability: ±30ppm

## Sheet TIDA-00462_E1_TID_Hardware.SchDoc: Hardware
size 431 x 279 mm; Date: Not shown in title block; ApprovedBy: Not shown in title block; CheckedBy: Not shown in title block; Author: Not shown in title block; CompanyName: Not shown in title block; DrawnBy: SY; Engineer: FA&C; Organization: Not shown in title block; Address1: Not shown in title block; Address2: Not shown in title block; Address3: Not shown in title block; Address4: Not shown in title block; DocumentNumber: 1; Revision: Use project parameter SCH_Rev; SheetNumber: 4; SheetTotal: 4; PageSetup: Record=PageOptions¦CenterHorizontal=True¦CenterVertical=True¦PrintScale=1.00¦XCorrection=1.00¦YCorrection=1.00¦PrintKind=0¦BorderSize=5000000¦LeftOffset=0¦BottomOffset=0¦Orientation=2¦PaperLength=1000¦PaperWidth=1000¦Scale=100¦PaperSource=15¦PrintQuality=600¦MediaType=1¦DitherType=10¦PaperKind=Letter¦PrintScaleMode=1
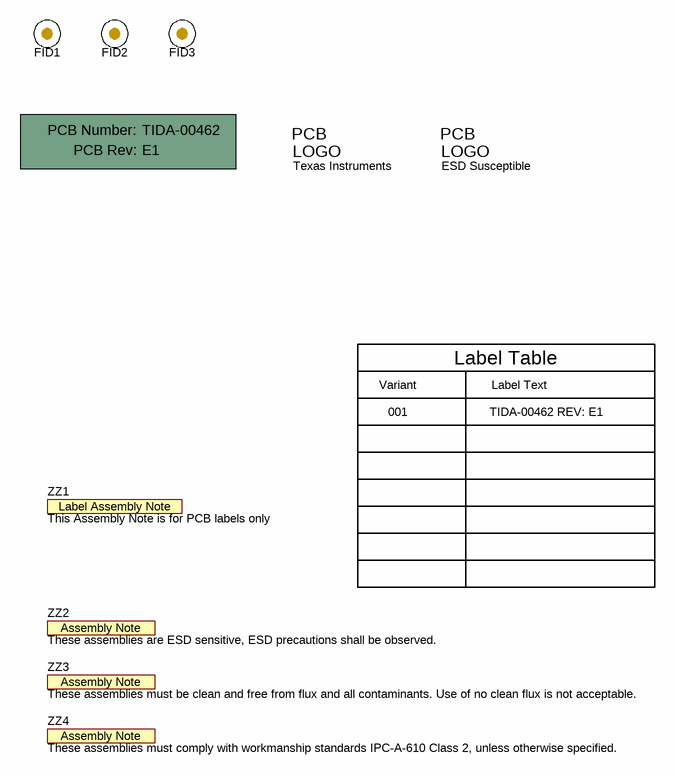
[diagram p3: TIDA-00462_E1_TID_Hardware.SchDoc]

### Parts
!PCB1  Printed Circuit Board  (value not drawn)  (mechanical)
FID1  Fiducial  [Fiducial10-20]  (value not drawn)
FID2  Fiducial  [Fiducial10-20]  (value not drawn)
FID3  Fiducial  [Fiducial10-20]  (value not drawn)
Logo1  Texas Instruments  [TI_Stacked_Overlay_Medium_Vertical]  (no BOM)
Logo2  ESD Susceptible  [ESD_Overlay_Large]  (no BOM)
ZZ1  This Assembly Note is for PCB labels only  [AssemblyNoteLabel]  (no BOM)
ZZ2  These assemblies are ESD sensitive, ESD precautions shall be observed.  [AssemblyNote]  (no BOM)
ZZ3  These assemblies must be clean and free from flux and all contaminants. Use of no clean flux is not acceptable.  [AssemblyNote]  (no BOM)
ZZ4  These assemblies must comply with workmanship standards IPC-A-610 Class 2, unless otherwise specified.  [AssemblyNote]  (no BOM)

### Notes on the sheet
- Label Table
- Variant
- 001
- Label Text
- TIDA-00462 REV: E1

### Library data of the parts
!PCB1 = PCB: Manufacturer: Any; PartNumber: TIDA-00462; SymbolCreator: a0412235
FID1-FID3 = Fiducial: Fiducial mark.  There is nothing to buy or mount.; SymbolCreator: codlsc
Logo1 = TI_Logo: Texas Instrument Corporate Signature; SymbolCreator: codlsc
Logo2 = ESD_Susceptible: ESD Susceptible Symbol; SymbolCreator: a0412235
ZZ1 = AssemblyNoteLabel: SymbolCreator: a0412235
ZZ2-ZZ4 = AssemblyNote: SymbolCreator: codlsc

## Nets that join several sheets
+3.3V: TIDA-00462_E1_Power_Supply (J6.2 J7.2 J19.2), TIDA-00462_E1_MCU_US_TX_RX (6 pins)
GND: TIDA-00462_E1_Power_Supply (17 pins), TIDA-00462_E1_MCU_US_TX_RX (32 pins)
V_OUT: TIDA-00462_E1_Power_Supply (5 pins), TIDA-00462_E1_MCU_US_TX_RX (C8.1 R6.2 U3.1)
BSL_RX: TIDA-00462_E1_Power_Supply (J20.14), TIDA-00462_E1_MCU_US_TX_RX (U4.35)
BSL_TX: TIDA-00462_E1_Power_Supply (J20.12), TIDA-00462_E1_MCU_US_TX_RX (U4.36)
COM_INV: TIDA-00462_E1_Power_Supply (J23.1), TIDA-00462_E1_MCU_US_TX_RX (U4.22)
LCD_EN: TIDA-00462_E1_Power_Supply (J24.2), TIDA-00462_E1_MCU_US_TX_RX (U4.13)
LCD_PWR_CNTL: TIDA-00462_E1_Power_Supply (J22.2), TIDA-00462_E1_MCU_US_TX_RX (U4.12)
LCD_SPI_CS: TIDA-00462_E1_Power_Supply (J25.2), TIDA-00462_E1_MCU_US_TX_RX (U4.14)
SBWTCK: TIDA-00462_E1_Power_Supply (J20.7), TIDA-00462_E1_MCU_US_TX_RX (U4.32)
SBWTDIO: TIDA-00462_E1_Power_Supply (J18.1 J20.1), TIDA-00462_E1_MCU_US_TX_RX (R16.1 U4.33)
SPI_CLK: TIDA-00462_E1_Power_Supply (J8.13), TIDA-00462_E1_MCU_US_TX_RX (U4.4)
SPI_CS: TIDA-00462_E1_Power_Supply (J9.6), TIDA-00462_E1_MCU_US_TX_RX (U4.1)
SPI_SIMO: TIDA-00462_E1_Power_Supply (J9.12), TIDA-00462_E1_MCU_US_TX_RX (U4.5)
SPI_SOMI: TIDA-00462_E1_Power_Supply (J9.14), TIDA-00462_E1_MCU_US_TX_RX (U4.6)
START: TIDA-00462_E1_Power_Supply (J8.14), TIDA-00462_E1_MCU_US_TX_RX (U4.9)
STOP: TIDA-00462_E1_Power_Supply (J9.1), TIDA-00462_E1_MCU_US_TX_RX (J17.1 U4.30)
TRIGGER: TIDA-00462_E1_Power_Supply (J8.12), TIDA-00462_E1_MCU_US_TX_RX (U4.3)

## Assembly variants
001: not fitted FID1 FID2 FID3 J10 J11 J12 J13 J14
